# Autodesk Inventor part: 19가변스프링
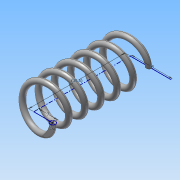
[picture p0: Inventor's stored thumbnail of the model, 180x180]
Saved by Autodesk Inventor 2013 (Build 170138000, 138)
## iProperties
Created: 2020-02
Part Number: 19가변스프링
Material: 강철
Document SubType Name: Modeling
Designer: Administrator
Density: 7.85 g/cm^3
Mass: 6.42535 g
Surface Area: 16.6087 cm^2
Volume: 0.818516 cm^3
Author: Administrator
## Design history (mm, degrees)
sketch "스케치1"
  geometry: L1 (0, 0)-(0, 35.5); L2 (0, 0)-(7, 0); L3 (0, 35.5)-(15, 35.5); C1 r 1 at (7, 0)
  constraints: 6 end point, 1 centre point, 1 coincident, 1 parallel, 1 perpendicular, 1 vertical
  dimensions: "d0" = 35.5 distance of L1.start L1.end (derived); "d1" = 7 distance of L1.start L2.end; "d2" = 15 distance of L1.end L3.end; "d3" = 2 diameter of C1
feature "코일1" pitch "d4" = 10; turns "d6" = 6; dims "d5" = 35.5 (= d0), "d7" = 0, angle "d8" = 90 deg, angle "d9" = 90 deg, "d10" = 0, "d11" = 0
sketch "스케치2"
  geometry: L1 (35.5, 15)-(0, 15); L2 (0, 15)-(0, -15); L3 (0, -15)-(35.5, -15); L4 (35.5, -15)-(35.5, 15); 2 further points
  constraints: 8 end point, 2 parallel, 1 coincident, 1 horizontal, 1 midpoint, 1 perpendicular
  dimensions: "d12" = 30 distance of L3.end L1.start; "d14" = 35.5 distance of L1.start L1.end (= d0)
extrude "돌출1" sketch "스케치2" stored distance "d15" = 30; taper "d16" = 0 deg
node "솔리드1"
